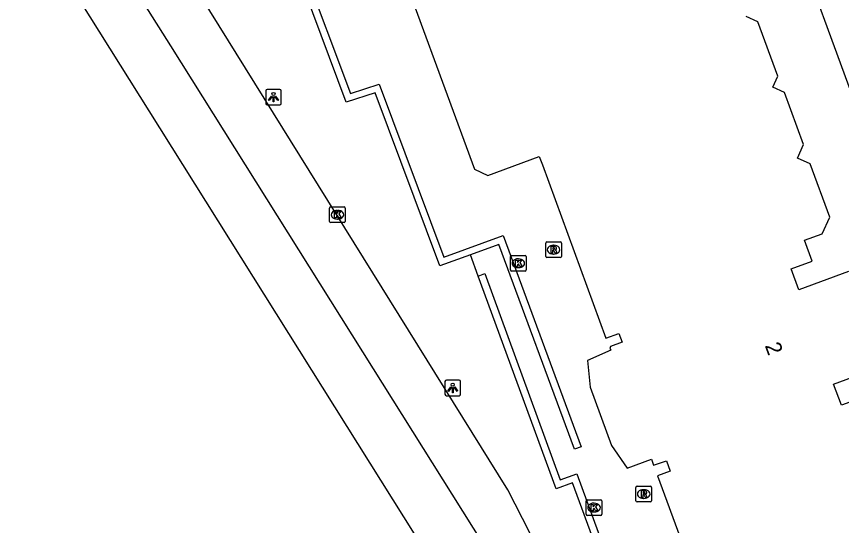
# Model space of a CAD drawing. Extents: x 160806 to 161707, y 383697 to 384148.
# Drawn here: x 160903.7 to 160956.3, y 383884.9 to 383917.3 of the extents above; entities that cross this region are included whole.
import ezdxf

# ---------------------------------------------------------------- set-up
doc = ezdxf.new("R2010")
doc.units = 0
for name, color, linetype in [('IMGEO_Kolk', 7, 'Continuous'), ('IMGEO_Lichtpunt', 7, 'Continuous'), ('IMGEO_Muur', 7, 'Continuous'), ('IMGEO_Pand', 7, 'Continuous'), ('IMGEO_Pand_nummerreeks', 7, 'Continuous'), ('IMGEO_Rijbaan_lokaal_gesloten', 7, 'Continuous'), ('IMGEO_Rijbaan_lokaal_open', 7, 'Continuous'), ('IMGEO_Rioolput', 7, 'Continuous'), ('IMGEO_Voetpad_open', 7, 'Continuous')]:
    doc.layers.add(name, color=color, linetype=linetype)

msp = doc.modelspace()

# ---------------------------------------------------------------- linework, layer by layer
at = {"layer": 'IMGEO_Kolk'}
for p, q in [((160923.69, 383904.258), (160923.69, 383905.11)), ((160923.765, 383905.184), (160924.617, 383905.184)), ((160924.691, 383905.11), (160924.691, 383904.258)), ((160924.178, 383904.964), (160924.203, 383904.964)), ((160924.617, 383904.184), (160923.765, 383904.184)), ((160924.201, 383904.404), (160924.176, 383904.404)), ((160935.224, 383901.166), (160935.224, 383902.018)), ((160935.299, 383902.092), (160936.151, 383902.092)), ((160935.712, 383901.872), (160935.737, 383901.872)), ((160936.225, 383902.018), (160936.225, 383901.166)), ((160935.735, 383901.312), (160935.71, 383901.312)), ((160936.151, 383901.092), (160935.299, 383901.092)), ((160940.052, 383885.582), (160940.052, 383886.434)), ((160940.127, 383886.508), (160940.979, 383886.508)), ((160940.54, 383886.288), (160940.565, 383886.288)), ((160941.053, 383886.434), (160941.053, 383885.582)), ((160940.563, 383885.728), (160940.538, 383885.728)), ((160940.979, 383885.508), (160940.127, 383885.508))]:
    msp.add_line(p, q, dxfattribs=at)
for points in [[(160923.69, 383904.258), (160923.69, 383905.11)], [(160923.765, 383905.184), (160924.617, 383905.184)], [(160924.691, 383905.11), (160924.691, 383904.258)], [(160924.011, 383904.884), (160924.134, 383904.884), (160924.134, 383904.733), (160924.264, 383904.884), (160924.428, 383904.884), (160924.282, 383904.733), (160924.435, 383904.484), (160924.283, 383904.484), (160924.198, 383904.648), (160924.134, 383904.581), (160924.134, 383904.484), (160924.011, 383904.484), (160924.011, 383904.884)], [(160924.617, 383904.184), (160923.765, 383904.184)], [(160935.224, 383901.166), (160935.224, 383902.018)], [(160935.299, 383902.092), (160936.151, 383902.092)], [(160936.225, 383902.018), (160936.225, 383901.166)], [(160935.545, 383901.792), (160935.668, 383901.792), (160935.668, 383901.641), (160935.798, 383901.792), (160935.962, 383901.792), (160935.816, 383901.641), (160935.969, 383901.392), (160935.817, 383901.392), (160935.732, 383901.556), (160935.668, 383901.489), (160935.668, 383901.392), (160935.545, 383901.392), (160935.545, 383901.792)], [(160936.151, 383901.092), (160935.299, 383901.092)], [(160940.052, 383885.582), (160940.052, 383886.434)], [(160940.127, 383886.508), (160940.979, 383886.508)], [(160940.373, 383886.208), (160940.496, 383886.208), (160940.496, 383886.057), (160940.626, 383886.208), (160940.79, 383886.208), (160940.644, 383886.057), (160940.797, 383885.808), (160940.645, 383885.808), (160940.56, 383885.972), (160940.496, 383885.905), (160940.496, 383885.808), (160940.373, 383885.808), (160940.373, 383886.208)], [(160941.053, 383886.434), (160941.053, 383885.582)], [(160940.979, 383885.508), (160940.127, 383885.508)]]:
    msp.add_lwpolyline(points, dxfattribs=at)
for centre, start, end in [((160923.767, 383905.108), 91.552, 178.448), ((160923.767, 383905.108), 91.552, 178.448), ((160924.615, 383905.108), 1.552, 88.448), ((160924.615, 383905.108), 1.552, 88.448), ((160923.767, 383904.26), 181.552, 268.448), ((160923.767, 383904.26), 181.552, 268.448), ((160924.615, 383904.26), 271.552, 358.448), ((160924.615, 383904.26), 271.552, 358.448), ((160935.301, 383902.016), 91.552, 178.448), ((160935.301, 383902.016), 91.552, 178.448), ((160936.149, 383902.016), 1.552, 88.448), ((160936.149, 383902.016), 1.552, 88.448), ((160935.301, 383901.168), 181.552, 268.448), ((160935.301, 383901.168), 181.552, 268.448), ((160936.149, 383901.168), 271.552, 358.448), ((160936.149, 383901.168), 271.552, 358.448), ((160940.129, 383886.432), 91.552, 178.448), ((160940.129, 383886.432), 91.552, 178.448), ((160940.977, 383886.432), 1.552, 88.448), ((160940.977, 383886.432), 1.552, 88.448), ((160940.129, 383885.584), 181.552, 268.448), ((160940.129, 383885.584), 181.552, 268.448), ((160940.977, 383885.584), 271.552, 358.448), ((160940.977, 383885.584), 271.552, 358.448)]:
    msp.add_arc(centre, 0.0765, start, end, dxfattribs=at)
for centre, major_axis, ratio, start_param, end_param in [((160924.177, 383904.684), (-0.387, 0.002), 0.722429, 4.712389, 7.853982), ((160924.202, 383904.684), (-0.39, 0.002), 0.717154, 1.570796, 4.712389), ((160935.711, 383901.592), (-0.387, 0.002), 0.722429, 4.712389, 7.853982), ((160935.736, 383901.592), (-0.39, 0.002), 0.717154, 1.570796, 4.712389), ((160940.539, 383886.008), (-0.387, 0.002), 0.722429, 4.712389, 7.853982), ((160940.564, 383886.008), (-0.39, 0.002), 0.717154, 1.570796, 4.712389)]:
    msp.add_ellipse(centre, major_axis=major_axis, ratio=ratio, start_param=start_param, end_param=end_param, dxfattribs=at)
at = {"layer": 'IMGEO_Lichtpunt'}
for p, q in [((160919.613, 383912.588), (160919.613, 383911.781)), ((160919.613, 383912.588), (160919.613, 383911.781)), ((160920.515, 383912.683), (160919.707, 383912.683)), ((160920.515, 383912.683), (160919.707, 383912.683)), ((160920.609, 383911.781), (160920.609, 383912.588)), ((160920.609, 383911.781), (160920.609, 383912.588)), ((160919.707, 383911.687), (160920.515, 383911.687)), ((160919.707, 383911.687), (160920.515, 383911.687)), ((160931.043, 383894.042), (160931.043, 383893.235)), ((160931.043, 383894.042), (160931.043, 383893.235)), ((160931.945, 383894.137), (160931.137, 383894.137)), ((160931.945, 383894.137), (160931.137, 383894.137)), ((160932.039, 383893.235), (160932.039, 383894.042)), ((160932.039, 383893.235), (160932.039, 383894.042)), ((160931.137, 383893.141), (160931.945, 383893.141)), ((160931.137, 383893.141), (160931.945, 383893.141))]:
    msp.add_line(p, q, dxfattribs=at)
for points in [[(160919.987, 383912.252), (160920.026, 383912.224), (160919.838, 383911.962), (160919.8, 383911.989), (160919.987, 383912.252)], [(160920.089, 383912.204), (160920.136, 383912.204), (160920.136, 383911.882), (160920.089, 383911.882), (160920.089, 383912.204)], [(160920.199, 383912.224), (160920.237, 383912.251), (160920.424, 383911.989), (160920.385, 383911.961), (160920.199, 383912.224)], [(160931.417, 383893.706), (160931.456, 383893.678), (160931.268, 383893.416), (160931.23, 383893.443), (160931.417, 383893.706)], [(160931.519, 383893.658), (160931.566, 383893.658), (160931.566, 383893.336), (160931.519, 383893.336), (160931.519, 383893.658)], [(160931.629, 383893.678), (160931.667, 383893.705), (160931.854, 383893.443), (160931.815, 383893.415), (160931.629, 383893.678)]]:
    msp.add_lwpolyline(points, dxfattribs=at)
for centre in [(160920.112, 383912.386), (160931.542, 383893.84)]:
    msp.add_circle(centre, 0.0994, dxfattribs=at)
for centre, start, end in [((160919.707, 383912.588), 90, 180), ((160919.707, 383912.588), 90, 180), ((160920.515, 383912.588), 0, 90), ((160920.515, 383912.588), 0, 90), ((160919.707, 383911.781), 180, 270), ((160919.707, 383911.781), 180, 270), ((160920.515, 383911.781), 270, 0), ((160920.515, 383911.781), 270, 360), ((160931.137, 383894.042), 90, 180), ((160931.137, 383894.042), 90, 180), ((160931.945, 383894.042), 0, 90), ((160931.945, 383894.042), 0, 90), ((160931.137, 383893.235), 180, 270), ((160931.137, 383893.235), 180, 270), ((160931.945, 383893.235), 270, 0), ((160931.945, 383893.235), 270, 360)]:
    msp.add_arc(centre, 0.0946, start, end, dxfattribs=at)
at = {"layer": 'IMGEO_Muur'}
for points in [[(160932.668, 383902.136), (160930.711, 383901.426), (160926.589, 383912.466), (160924.748, 383911.86), (160917.241, 383931.994)], [(160921.944, 383920.655), (160925.013, 383912.411), (160926.853, 383913.016), (160930.971, 383901.988), (160934.751, 383903.36), (160939.722, 383889.883), (160939.309, 383889.731), (160934.489, 383902.797), (160932.668, 383902.136)], [(160933.165, 383900.776), (160933.578, 383900.927), (160938.39, 383887.768), (160939.444, 383888.153), (160943.859, 383876.128), (160945.05, 383876.564), (160950.202, 383862.823), (160953.064, 383863.812), (160955.689, 383856.974), (160961.572, 383859.068), (160963.971, 383852.576), (160986.298, 383860.697), (160987.492, 383857.138), (160995.069, 383859.96)], [(160963.71, 383852.014), (160961.31, 383858.508), (160955.432, 383856.416), (160952.806, 383863.257), (160949.941, 383862.267), (160944.791, 383876.001), (160943.598, 383875.564), (160939.182, 383887.589), (160938.128, 383887.204), (160933.165, 383900.776)]]:
    msp.add_lwpolyline(points, dxfattribs=at)
at = {"layer": 'IMGEO_Pand'}
for points in [[(160929.143, 383917.874), (160932.92, 383907.588), (160933.777, 383907.191), (160937.059, 383908.396), (160937.257, 383907.858), (160941.311, 383896.815), (160942.138, 383897.119), (160942.343, 383896.56), (160941.61, 383896.291), (160941.567, 383896.161), (160941.612, 383896.038), (160940.145, 383895.381), (160940.299, 383893.68), (160941.665, 383889.958), (160942.668, 383888.523), (160944.216, 383889.087), (160944.282, 383888.903), (160944.348, 383888.721), (160945.168, 383888.982), (160945.408, 383888.328), (160944.607, 383888.034), (160952.308, 383867.059)], [(160956.781, 383901.058), (160953.618, 383899.896), (160953.124, 383901.241), (160954.453, 383901.73), (160953.966, 383903.056), (160955.102, 383903.473), (160955.587, 383904.522), (160954.338, 383907.923), (160953.519, 383908.302), (160953.915, 383909.158), (160952.694, 383912.486), (160951.954, 383912.828), (160952.275, 383913.522), (160951, 383916.994), (160950.257, 383917.338)], [(160957.559, 383892.984), (160956.324, 383892.531), (160955.83, 383893.878), (160958.991, 383895.039)]]:
    msp.add_lwpolyline(points, dxfattribs=at)
at = {"layer": 'IMGEO_Rijbaan_lokaal_gesloten'}
for points in [[(160936.803, 383883.721), (160935.997, 383885.302), (160935.062, 383887.143), (160909.71, 383927.9)], [(160945.002, 383865.641), (160938.564, 383875.623), (160925.814, 383895.944), (160913.566, 383915.455), (160908.015, 383924.267), (160906.682, 383926.368)], [(160955.934, 383835.901), (160955.876, 383837.546), (160955.019, 383841.251), (160954.11, 383843.892), (160952.745, 383846.411), (160950.252, 383850.619), (160927.745, 383886.505), (160912.866, 383910.221), (160906.479, 383920.419), (160903.723, 383924.87)]]:
    msp.add_lwpolyline(points, dxfattribs=at)
at = {"layer": 'IMGEO_Rijbaan_lokaal_open'}
msp.add_lwpolyline([(161034.783, 383900.781), (161000, 383887.972), (160991.432, 383884.817), (160990.275, 383885.032), (160986.341, 383885.715), (160984.869, 383885.974), (160968.05, 383879.828), (160959.806, 383902.516), (160960.137, 383903.811), (160950.161, 383931.007)], dxfattribs=at)
at = {"layer": 'IMGEO_Rioolput'}
for p, q in [((160937.47, 383902.029), (160937.47, 383902.881)), ((160937.545, 383902.955), (160938.397, 383902.955)), ((160938.471, 383902.881), (160938.471, 383902.029)), ((160937.958, 383902.735), (160937.983, 383902.735)), ((160938.397, 383901.955), (160937.545, 383901.955)), ((160937.981, 383902.175), (160937.956, 383902.175)), ((160943.22, 383886.443), (160943.22, 383887.295)), ((160943.295, 383887.369), (160944.147, 383887.369)), ((160943.708, 383887.149), (160943.733, 383887.149)), ((160944.221, 383887.295), (160944.221, 383886.443)), ((160943.731, 383886.589), (160943.706, 383886.589)), ((160944.147, 383886.369), (160943.295, 383886.369))]:
    msp.add_line(p, q, dxfattribs=at)
for points in [[(160937.47, 383902.029), (160937.47, 383902.881)], [(160937.545, 383902.955), (160938.397, 383902.955)], [(160938.471, 383902.881), (160938.471, 383902.029)], [(160938.059, 383902.653), (160937.807, 383902.655), (160937.807, 383902.255)], [(160937.807, 383902.255), (160937.931, 383902.255), (160937.931, 383902.417), (160937.942, 383902.417)], [(160937.985, 383902.574), (160937.931, 383902.574), (160937.931, 383902.493)], [(160937.931, 383902.493), (160937.983, 383902.493)], [(160937.989, 383902.388), (160938.06, 383902.255), (160938.2, 383902.255), (160938.135, 383902.381)], [(160938.397, 383901.955), (160937.545, 383901.955)], [(160943.22, 383886.443), (160943.22, 383887.295)], [(160943.295, 383887.369), (160944.147, 383887.369)], [(160944.221, 383887.295), (160944.221, 383886.443)], [(160943.809, 383887.067), (160943.557, 383887.069), (160943.557, 383886.669)], [(160943.557, 383886.669), (160943.681, 383886.669), (160943.681, 383886.831), (160943.692, 383886.831)], [(160943.735, 383886.988), (160943.681, 383886.988), (160943.681, 383886.907)], [(160943.681, 383886.907), (160943.733, 383886.907)], [(160943.739, 383886.802), (160943.81, 383886.669), (160943.95, 383886.669), (160943.885, 383886.795)], [(160944.147, 383886.369), (160943.295, 383886.369)]]:
    msp.add_lwpolyline(points, dxfattribs=at)
for centre, radius, start, end in [((160937.547, 383902.879), 0.0765, 91.552, 178.448), ((160937.547, 383902.879), 0.0765, 91.552, 178.448), ((160938.395, 383902.879), 0.0765, 1.552, 88.448), ((160938.395, 383902.879), 0.0765, 1.552, 88.448), ((160937.941, 383902.364), 0.0533, 26.0293, 88.6989), ((160937.967, 383902.682), 0.19, 274.7715, 282.9687), ((160937.991, 383902.478), 0.0964, 77.0061, 93.1865), ((160938.005, 383902.535), 0.0378, 276.6634, 79.6772), ((160938.058, 383902.543), 0.109, 350.3612, 89.416), ((160938.056, 383902.543), 0.112, 277.5842, 350.9817), ((160938.04, 383902.328), 0.108, 29.5134, 73.7905), ((160937.547, 383902.031), 0.0765, 181.552, 268.448), ((160937.547, 383902.031), 0.0765, 181.552, 268.448), ((160938.395, 383902.031), 0.0765, 271.552, 358.448), ((160938.395, 383902.031), 0.0765, 271.552, 358.448), ((160943.297, 383887.293), 0.0765, 91.552, 178.448), ((160943.297, 383887.293), 0.0765, 91.552, 178.448), ((160944.145, 383887.293), 0.0765, 1.552, 88.448), ((160944.145, 383887.293), 0.0765, 1.552, 88.448), ((160943.691, 383886.778), 0.0533, 26.0293, 88.6989), ((160943.717, 383887.096), 0.19, 274.7715, 282.9687), ((160943.741, 383886.892), 0.0964, 77.0061, 93.1865), ((160943.755, 383886.949), 0.0378, 276.6634, 79.6772), ((160943.808, 383886.957), 0.109, 350.3612, 89.416), ((160943.806, 383886.957), 0.112, 277.5842, 350.9817), ((160943.79, 383886.742), 0.108, 29.5134, 73.7905), ((160943.297, 383886.445), 0.0765, 181.552, 268.448), ((160943.297, 383886.445), 0.0765, 181.552, 268.448), ((160944.145, 383886.445), 0.0765, 271.552, 358.448), ((160944.145, 383886.445), 0.0765, 271.552, 358.448)]:
    msp.add_arc(centre, radius, start, end, dxfattribs=at)
for centre, major_axis, ratio, start_param, end_param in [((160937.957, 383902.455), (-0.387, 0.002), 0.722429, 4.712389, 7.853982), ((160937.982, 383902.455), (-0.39, 0.002), 0.717154, 1.570796, 4.712389), ((160943.707, 383886.869), (-0.387, 0.002), 0.722429, 4.712389, 7.853982), ((160943.732, 383886.869), (-0.39, 0.002), 0.717154, 1.570796, 4.712389)]:
    msp.add_ellipse(centre, major_axis=major_axis, ratio=ratio, start_param=start_param, end_param=end_param, dxfattribs=at)
at = {"layer": 'IMGEO_Voetpad_open'}
msp.add_lwpolyline([(160933.165, 383900.776), (160932.668, 383902.136)], dxfattribs=at)

# ---------------------------------------------------------------- texts
at = {"layer": 'IMGEO_Pand_nummerreeks'}
msp.add_text('2', height=1, rotation=290.1794, dxfattribs=at).set_placement((160951.432, 383896.339))

doc.saveas('drawing.dxf')
